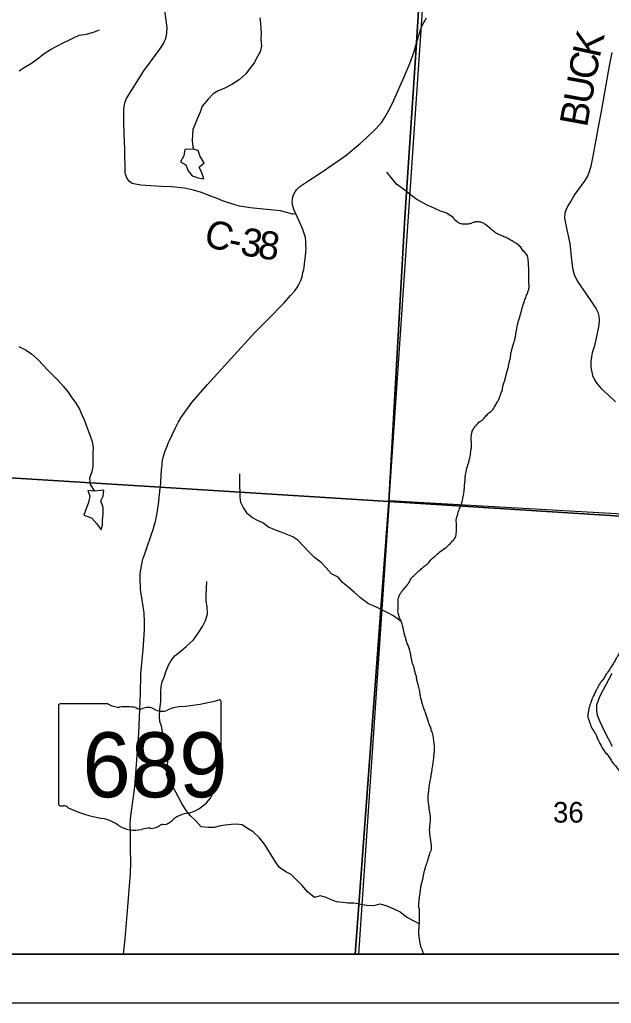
# Model space of a CAD drawing. Extents: x -13.7 to 34, y 0 to 32.3.
# Drawn here: x 24.869 to 26.069, y 14 to 15.995 of the extents above; entities that cross this region are included whole.
import ezdxf

# ---------------------------------------------------------------- set-up
doc = ezdxf.new("R2010")
doc.units = 0
for name, color, linetype in [('GM_X_Corporation', 7, 'Continuous'), ('GM_X_County_Road', 7, 'Continuous'), ('GM_X_County_Road_Text', 7, 'Continuous'), ('GM_X_Minor_Lake', 7, 'Continuous'), ('GM_X_Minor_River', 7, 'Continuous'), ('GM_X_Section_Text', 7, 'Continuous'), ('GM_X_State_Location', 7, 'Continuous'), ('GM_X_State_Route', 7, 'Continuous'), ('GM_X_State_Shield', 7, 'Continuous'), ('GM_X_Township_Road', 7, 'Continuous'), ('GM_X_Township_Road_Text', 7, 'Continuous'), ('SH_Data', 7, 'Continuous')]:
    doc.layers.add(name, color=color, linetype=linetype)

msp = doc.modelspace()

# ---------------------------------------------------------------- linework, layer by layer
at = {"layer": 'GM_X_Corporation'}
for points in [[(23.5167, 20.9), (23.5167, 14.1), (25.5491, 14.1), (25.6174, 15.0182), (25.6502, 15.5943), (25.6733, 15.948), (25.6857, 16.1459)], [(23.5167, 20.9), (23.5167, 15.1495), (24.0951, 15.113), (24.5995, 15.0813), (25.154, 15.0469), (25.6174, 15.0182), (25.6502, 15.5943), (25.6733, 15.948), (25.6857, 16.1459)], [(25.6857, 16.1459), (25.6733, 15.948), (25.6502, 15.5943), (25.6174, 15.0182), (25.5491, 14.1), (30.3167, 14.1)], [(25.6857, 16.1459), (25.6733, 15.948), (25.6502, 15.5943), (25.6174, 15.0182), (26.2581, 14.9774), (26.847, 14.9399), (27.6886, 14.8962), (28.6553, 14.8354)]]:
    msp.add_lwpolyline(points, dxfattribs=at)
for points in [[(25.6876, 16.0444), (26.7165, 15.9781), (26.6464, 14.9606), (25.6185, 15.0191)], [(23.5167, 15.1495), (23.5167, 14.1), (25.5491, 14.1), (25.6174, 15.0182), (25.154, 15.0469), (24.5995, 15.0813), (24.0951, 15.113)], [(25.5491, 14.1), (30.3167, 14.1), (30.3167, 14.7354), (29.7019, 14.7755), (28.6553, 14.8354), (27.6886, 14.8962), (26.847, 14.9399), (26.2581, 14.9774), (25.6174, 15.0182)], [(25.5561, 14.1), (26.5888, 14.1), (26.6464, 14.9606), (25.6185, 15.0191)]]:
    msp.add_lwpolyline(points, close=True, dxfattribs=at)
at = {"layer": 'GM_X_County_Road'}
msp.add_lwpolyline([(25.4287, 15.6011), (25.4223, 15.601), (25.4104, 15.6044), (25.398, 15.6076), (25.3837, 15.6091), (25.3633, 15.6112), (25.3366, 15.6138), (25.315, 15.6171), (25.3053, 15.6197), (25.2824, 15.6271), (25.2657, 15.6338), (25.2523, 15.6384), (25.2374, 15.6444), (25.2212, 15.6497), (25.2029, 15.6538), (25.1769, 15.6559), (25.1559, 15.6567), (25.1237, 15.6588), (25.1149, 15.6597), (25.1036, 15.6613), (25.097, 15.6628), (25.0918, 15.6672), (25.0875, 15.6716), (25.0853, 15.6762), (25.083, 15.6837), (25.082, 15.733), (25.081, 15.7619), (25.0799, 15.7886), (25.0799, 15.8015), (25.0802, 15.814), (25.0823, 15.8267), (25.0853, 15.8354), (25.1208, 15.8912), (25.1435, 15.9225), (25.153, 15.9351), (25.1597, 15.9454), (25.1618, 15.9501), (25.1643, 15.956), (25.1664, 15.9629), (25.1676, 15.9689), (25.1679, 15.9781), (25.1672, 15.9843), (25.1584, 16.0491)], dxfattribs=at)
at = {"layer": 'GM_X_Minor_Lake'}
for points in [[(25.2037, 15.7316), (25.2018, 15.7191), (25.195, 15.7069), (25.2056, 15.7005), (25.2106, 15.6884), (25.2186, 15.6785), (25.2265, 15.676)], [(25.2265, 15.676), (25.2303, 15.6747), (25.242, 15.6725), (25.2382, 15.6846), (25.2329, 15.696), (25.2428, 15.7051), (25.2348, 15.7176), (25.231, 15.7297), (25.2208, 15.7328), (25.2037, 15.7316)], [(25.0393, 15.0406), (25.0208, 15.0388), (25.0068, 15.0399), (25.0109, 15.0285), (25.0082, 15.0156), (25.0037, 15.0028), (24.9987, 14.9902), (25.0142, 14.9849), (25.02, 14.9787)], [(25.02, 14.9787), (25.0256, 14.9728), (25.0339, 14.9602), (25.0369, 14.9697), (25.037, 14.9803), (25.0381, 14.9925), (25.0381, 15.0057), (25.0336, 15.019), (25.0382, 15.0285), (25.0393, 15.0406)]]:
    msp.add_lwpolyline(points, dxfattribs=at)
at = {"layer": 'GM_X_Minor_River'}
for points in [[(25.3557, 15.9992), (25.3572, 15.9874), (25.358, 15.9779), (25.3583, 15.9681), (25.358, 15.9548), (25.3591, 15.9419), (25.3565, 15.9302), (25.3512, 15.9207), (25.3444, 15.9078), (25.335, 15.8952), (25.3274, 15.8857), (25.3138, 15.8732), (25.2994, 15.8637), (25.2839, 15.8557), (25.2714, 15.8508), (25.2615, 15.8447), (25.2513, 15.8337), (25.2392, 15.8196), (25.2347, 15.8079), (25.2294, 15.7953), (25.2241, 15.7821)], [(24.8679, 15.8912), (24.8781, 15.898), (24.8929, 15.9068), (24.905, 15.9159), (24.9186, 15.9269), (24.9311, 15.9349), (24.9444, 15.9413), (24.9569, 15.9482), (24.9675, 15.9527), (24.9781, 15.9584), (24.9894, 15.9638), (25.0042, 15.9661), (25.0208, 15.9703), (25.0307, 15.9744)], [(25.2241, 15.7821), (25.2203, 15.7722), (25.2196, 15.7623), (25.2188, 15.7498), (25.2208, 15.7328)], [(25.6545, 15.6463), (25.6455, 15.653), (25.633, 15.6617), (25.622, 15.6749), (25.6132, 15.6859)], [(25.6545, 15.6463), (25.6753, 15.6302), (25.6949, 15.6199), (25.7077, 15.6142), (25.7214, 15.6074), (25.7347, 15.6033), (25.7472, 15.5953)], [(24.8672, 15.3326), (24.8823, 15.3246), (24.8926, 15.3174), (24.9054, 15.306), (24.9168, 15.2946), (24.9251, 15.2847), (24.9349, 15.2756), (24.947, 15.2631), (24.9576, 15.2513), (24.9674, 15.2399), (24.9753, 15.2274), (24.9825, 15.2175), (24.9901, 15.2053), (24.9957, 15.1924), (25.0002, 15.1822), (25.0036, 15.1727), (25.0078, 15.1621), (25.0127, 15.1491), (25.0157, 15.1393), (25.0179, 15.1268), (25.0171, 15.115), (25.0175, 15.1025), (25.0171, 15.0896), (25.0152, 15.0778), (25.0106, 15.0649), (25.0117, 15.0524)], [(25.5964, 14.8013), (25.5866, 14.806), (25.5764, 14.8106), (25.5601, 14.8227), (25.5472, 14.8337), (25.534, 14.8455), (25.5238, 14.8539), (25.5147, 14.8641), (25.5011, 14.871), (25.4905, 14.8832), (25.4803, 14.8942), (25.4671, 14.9041), (25.4561, 14.9151), (25.444, 14.928), (25.4331, 14.9398), (25.4229, 14.9459), (25.413, 14.9504), (25.399, 14.9558), (25.3861, 14.9603), (25.3733, 14.9661), (25.3623, 14.9744), (25.3513, 14.9797), (25.3407, 14.9851), (25.3309, 14.9927), (25.3222, 15.0064), (25.3177, 15.0158), (25.3162, 15.0268), (25.3162, 15.0371), (25.3155, 15.0496), (25.3151, 15.0625), (25.3152, 15.0743)], [(25.0117, 15.0524), (25.0208, 15.0388)], [(25.5562, 14.2021), (25.5464, 14.203), (25.5342, 14.203), (25.5244, 14.2045), (25.5115, 14.2061), (25.5013, 14.2099), (25.4881, 14.2156), (25.4782, 14.2183), (25.4665, 14.2149), (25.4525, 14.2263), (25.4419, 14.2388), (25.4302, 14.2502), (25.4196, 14.2612), (25.4086, 14.2666), (25.3958, 14.2757), (25.3893, 14.2852), (25.3806, 14.2981), (25.3735, 14.3099), (25.3652, 14.3228), (25.3553, 14.3357), (25.3425, 14.3479), (25.3311, 14.3547), (25.3198, 14.3623), (25.3088, 14.3635), (25.2978, 14.3627), (25.2853, 14.3612), (25.2758, 14.3601), (25.2633, 14.3567), (25.2508, 14.3564), (25.2372, 14.3579), (25.2259, 14.3701), (25.2149, 14.3807), (25.2074, 14.3906), (25.1987, 14.4039), (25.1923, 14.4153), (25.1855, 14.4286), (25.1802, 14.438), (25.1711, 14.451), (25.1666, 14.4639), (25.1681, 14.4783), (25.1693, 14.4889), (25.1705, 14.5033), (25.169, 14.517), (25.1667, 14.5299), (25.1633, 14.5393), (25.1588, 14.5507), (25.1562, 14.5621), (25.1528, 14.5716), (25.1521, 14.5815), (25.1532, 14.597), (25.1548, 14.6118), (25.1548, 14.6323), (25.1556, 14.6425), (25.1575, 14.652), (25.1621, 14.6619), (25.1659, 14.6744), (25.1704, 14.6857), (25.1761, 14.6952), (25.1845, 14.7054), (25.197, 14.716), (25.2065, 14.7236), (25.2213, 14.7376), (25.2308, 14.7509), (25.2399, 14.7641), (25.246, 14.7766), (25.2498, 14.7903), (25.2491, 14.8039), (25.2472, 14.8168), (25.2469, 14.8282), (25.248, 14.8419), (25.2484, 14.8555)], [(25.5964, 14.8013), (25.6146, 14.793), (25.6275, 14.7858), (25.6424, 14.7753)], [(25.5562, 14.2021), (25.5732, 14.1991), (25.5861, 14.1987), (25.6001, 14.2017), (25.6134, 14.1976), (25.6278, 14.1915), (25.6403, 14.1857), (25.6543, 14.1747), (25.6794, 14.1612)]]:
    msp.add_lwpolyline(points, dxfattribs=at)
for points in [[(25.7851, 15.126), (25.7851, 15.1325), (25.7848, 15.1405), (25.7848, 15.1485), (25.7853, 15.1545), (25.7868, 15.1606), (25.7907, 15.1674), (25.7956, 15.1739), (25.8021, 15.1799), (25.809, 15.1852), (25.8151, 15.1924), (25.8216, 15.1984), (25.8288, 15.2052), (25.8342, 15.2143), (25.8388, 15.2219), (25.8419, 15.2287), (25.8446, 15.2363), (25.8477, 15.2443), (25.8485, 15.2503), (25.8504, 15.2568), (25.8527, 15.2636), (25.8547, 15.2712), (25.8563, 15.278), (25.8586, 15.286), (25.8605, 15.2928), (25.8617, 15.2989), (25.8633, 15.3069), (25.8645, 15.313), (25.8656, 15.3205), (25.8672, 15.3266), (25.8688, 15.3335), (25.8715, 15.3422), (25.8738, 15.3498), (25.8754, 15.3581), (25.8762, 15.3646), (25.8777, 15.3718), (25.8793, 15.3801), (25.8809, 15.3862), (25.8836, 15.3946), (25.8855, 15.4006), (25.8871, 15.4075), (25.8913, 15.4207), (25.8944, 15.4298), (25.8979, 15.4386), (25.9002, 15.445), (25.9018, 15.4518), (25.9018, 15.4583), (25.9015, 15.4667), (25.9012, 15.4735), (25.9013, 15.4895), (25.9009, 15.4956), (25.9006, 15.5032), (25.8999, 15.51), (25.8984, 15.5165), (25.8935, 15.523), (25.8871, 15.5302), (25.8811, 15.5379), (25.8732, 15.5432), (25.8656, 15.5475), (25.8573, 15.5521), (25.8486, 15.5559), (25.8422, 15.5586), (25.8361, 15.5617), (25.8278, 15.5678), (25.8142, 15.5793), (25.8074, 15.5832), (25.8002, 15.5851), (25.7942, 15.5851), (25.7866, 15.5829), (25.7805, 15.581), (25.7733, 15.5803), (25.7649, 15.5808), (25.7589, 15.5831), (25.7521, 15.5888), (25.7472, 15.5953)], [(25.7012, 14.3637), (25.702, 14.3709), (25.7013, 14.3838), (25.6995, 14.3934), (25.6988, 14.4013), (25.6977, 14.4082), (25.6973, 14.4147), (25.6982, 14.4283), (25.699, 14.4356), (25.7014, 14.4507), (25.7025, 14.4568), (25.7037, 14.464), (25.7049, 14.4705), (25.7065, 14.4815), (25.7081, 14.4917), (25.7089, 14.5016), (25.7101, 14.5138), (25.7102, 14.5202), (25.7091, 14.5309), (25.7073, 14.5427), (25.7043, 14.553), (25.7017, 14.5606), (25.6987, 14.5686), (25.6961, 14.577), (25.6931, 14.585), (25.6902, 14.5937), (25.6868, 14.6032), (25.6846, 14.6109), (25.6827, 14.6181), (25.6809, 14.6276), (25.6798, 14.6352), (25.6769, 14.6466), (25.6746, 14.6558), (25.6728, 14.6649), (25.6706, 14.6718), (25.6691, 14.6801), (25.6665, 14.6874), (25.6639, 14.6969), (25.6624, 14.7045), (25.6613, 14.711), (25.6591, 14.7197), (25.6558, 14.7281), (25.6528, 14.7365), (25.6509, 14.7441), (25.6483, 14.7521), (25.6472, 14.7586), (25.645, 14.7666), (25.6424, 14.7753), (25.6391, 14.7822), (25.6372, 14.7894), (25.6361, 14.7955), (25.6365, 14.8027), (25.6362, 14.8103), (25.6362, 14.8164), (25.637, 14.8225), (25.6401, 14.8297), (25.644, 14.8357), (25.6493, 14.8418), (25.6562, 14.8501), (25.66, 14.8565), (25.6635, 14.863), (25.6704, 14.8694), (25.6765, 14.8754), (25.6841, 14.8819), (25.6902, 14.8872), (25.6967, 14.8924), (25.7039, 14.9011), (25.712, 14.9079), (25.7211, 14.9159), (25.7303, 14.9223), (25.7367, 14.9275), (25.7432, 14.934), (25.749, 14.9404), (25.7532, 14.9476), (25.7544, 14.9537), (25.7548, 14.9597), (25.7545, 14.9673), (25.7545, 14.9746), (25.7542, 14.9807), (25.7557, 14.9867), (25.7577, 14.9936), (25.7608, 15.0034), (25.765, 15.0137), (25.7669, 15.0209), (25.7689, 15.0307), (25.7705, 15.0406), (25.7709, 15.049), (25.7717, 15.0558), (25.7722, 15.0638), (25.773, 15.0721), (25.7741, 15.0782), (25.778, 15.0926), (25.78, 15.0987), (25.7815, 15.1055), (25.7831, 15.112), (25.7835, 15.1188), (25.7851, 15.126)], [(26.1283, 14.8845), (26.1244, 14.8735), (26.1202, 14.864), (26.1194, 14.8561), (26.119, 14.8496), (26.1178, 14.8424), (26.117, 14.8321), (26.1169, 14.8234), (26.115, 14.8158), (26.1142, 14.8086), (26.1126, 14.7999), (26.1114, 14.7915), (26.1106, 14.785), (26.109, 14.7782), (26.1078, 14.7706), (26.1059, 14.7634), (26.1039, 14.7562), (26.1005, 14.7498), (26.0982, 14.7422), (26.0955, 14.7342), (26.0924, 14.7262), (26.0866, 14.7149), (26.082, 14.7054), (26.0785, 14.6993), (26.0739, 14.691), (26.0686, 14.6827), (26.0632, 14.6736), (26.0582, 14.6675), (26.054, 14.66), (26.0483, 14.6524), (26.0437, 14.6459), (26.0406, 14.6395), (26.0371, 14.6334), (26.0337, 14.6255), (26.0302, 14.6187), (26.0271, 14.6099), (26.0248, 14.6035), (26.0229, 14.5963), (26.0217, 14.5887), (26.0212, 14.5799), (26.0235, 14.5731), (26.0272, 14.5628), (26.0317, 14.554), (26.0366, 14.5472), (26.0392, 14.5407), (26.0429, 14.5327), (26.0467, 14.5251), (26.0515, 14.5163), (26.0572, 14.5083), (26.0628, 14.5014), (26.0681, 14.493), (26.0733, 14.4861), (26.0805, 14.4773), (26.0865, 14.4705), (26.0925, 14.464), (26.1005, 14.4563), (26.1076, 14.4487), (26.1121, 14.4426), (26.1204, 14.4349), (26.1272, 14.4296), (26.1336, 14.4242), (26.1385, 14.4177), (26.1449, 14.4093), (26.1509, 14.4024), (26.1562, 14.3944), (26.1615, 14.3875), (26.1663, 14.3784), (26.1701, 14.3704), (26.1738, 14.3628), (26.1764, 14.3563), (26.1786, 14.3464), (26.1801, 14.3399), (26.182, 14.3308), (26.1834, 14.3236), (26.1845, 14.3175), (26.1856, 14.3114), (26.1856, 14.3023), (26.1863, 14.2931), (26.1877, 14.2848), (26.1888, 14.2775), (26.1891, 14.2688), (26.1898, 14.2593), (26.1902, 14.2532), (26.1909, 14.2444), (26.1916, 14.2384), (26.1946, 14.2285), (26.1976, 14.2224), (26.2024, 14.2117), (26.2058, 14.2052), (26.2099, 14.1983), (26.2133, 14.1922), (26.2189, 14.1846), (26.2227, 14.1777), (26.2272, 14.1716), (26.2305, 14.1613), (26.2328, 14.1534), (26.2339, 14.1469)]]:
    msp.add_spline(points, degree=3, dxfattribs=at)
msp.add_open_spline([(25.6884, 14.1), (25.6878, 14.1017), (25.6872, 14.1033), (25.6866, 14.1049), (25.6855, 14.1078), (25.6842, 14.1105), (25.6832, 14.1133), (25.6822, 14.1163), (25.6816, 14.1194), (25.681, 14.1225), (25.6806, 14.1245), (25.6802, 14.1265), (25.6799, 14.1285), (25.6795, 14.1313), (25.6791, 14.1341), (25.6788, 14.1369), (25.6785, 14.1403), (25.6784, 14.1438), (25.6785, 14.1472), (25.6787, 14.1519), (25.6792, 14.1565), (25.6794, 14.1612), (25.6795, 14.1658), (25.6797, 14.1704), (25.6798, 14.1749), (25.6799, 14.179), (25.6799, 14.183), (25.6799, 14.1871), (25.6799, 14.1911), (25.6777, 14.1949), (25.6781, 14.1989), (25.6783, 14.2017), (25.6786, 14.2044), (25.6789, 14.2072), (25.6792, 14.2101), (25.6794, 14.2131), (25.6797, 14.216), (25.68, 14.2185), (25.6806, 14.221), (25.6809, 14.2236), (25.6812, 14.2256), (25.6814, 14.2276), (25.6817, 14.2296), (25.6823, 14.2337), (25.6829, 14.2378), (25.6837, 14.2418), (25.6841, 14.2439), (25.6852, 14.2458), (25.6856, 14.2479), (25.6864, 14.2515), (25.6868, 14.2552), (25.6876, 14.2589), (25.6883, 14.2622), (25.6891, 14.2655), (25.6899, 14.2687), (25.6908, 14.2721), (25.6916, 14.2753), (25.6926, 14.2786), (25.6935, 14.2814), (25.6949, 14.2841), (25.6957, 14.287), (25.6967, 14.2901), (25.6975, 14.2933), (25.6985, 14.2964), (25.6993, 14.2995), (25.7003, 14.3025), (25.7012, 14.3055), (25.7018, 14.3078), (25.7033, 14.3097), (25.7039, 14.312), (25.7045, 14.3149), (25.7043, 14.3178), (25.7039, 14.3207), (25.7036, 14.3233), (25.7032, 14.3258), (25.7028, 14.3283), (25.7024, 14.3315), (25.7018, 14.3347), (25.7014, 14.3379), (25.701, 14.3405), (25.7009, 14.3432), (25.7007, 14.3458), (25.7005, 14.3485), (25.7001, 14.3512), (25.7003, 14.3538), (25.7006, 14.3571), (25.7009, 14.3604), (25.7012, 14.3637)], degree=3, dxfattribs=at)
at = {"layer": 'GM_X_State_Route'}
for points in [[(25.6735, 15.9475), (25.6819, 15.9745), (25.6859, 15.9845), (25.6942, 15.9987)], [(25.4287, 15.6011), (25.4246, 15.61), (25.422, 15.6197), (25.4217, 15.626), (25.4219, 15.6309), (25.4228, 15.6361), (25.4243, 15.6401), (25.4276, 15.6463), (25.4306, 15.6504), (25.437, 15.6568), (25.4532, 15.6677), (25.4725, 15.6799), (25.4932, 15.6941), (25.5303, 15.7197), (25.5596, 15.7442), (25.5709, 15.7542), (25.5911, 15.7737), (25.5973, 15.7808), (25.6032, 15.7873), (25.6104, 15.798), (25.616, 15.8087), (25.6249, 15.8257), (25.6484, 15.8791), (25.6599, 15.9064), (25.6686, 15.9307), (25.6735, 15.9475)], [(25.0793, 14.1), (25.0825, 14.131), (25.0884, 14.1958), (25.0915, 14.238), (25.0934, 14.2634), (25.0941, 14.2853), (25.0934, 14.3144), (25.0933, 14.3475), (25.0929, 14.3625), (25.0939, 14.3735), (25.0951, 14.385), (25.0982, 14.4095), (25.1008, 14.4288), (25.1026, 14.4394), (25.1105, 14.5478), (25.1126, 14.5957), (25.1137, 14.6283), (25.1145, 14.6679), (25.1159, 14.6833), (25.1195, 14.717), (25.1209, 14.7373), (25.1219, 14.7574), (25.1219, 14.771), (25.1219, 14.7795), (25.1216, 14.7863), (25.1211, 14.7914), (25.1206, 14.7965), (25.1191, 14.805), (25.1162, 14.8266), (25.1147, 14.8335), (25.1141, 14.8412), (25.1136, 14.8477), (25.1129, 14.8574), (25.1129, 14.8641), (25.1132, 14.87), (25.1136, 14.8763), (25.115, 14.8824), (25.116, 14.8876), (25.1177, 14.8975), (25.1193, 14.9033), (25.1217, 14.9094), (25.1293, 14.9321), (25.1327, 14.9418), (25.136, 14.9518), (25.1396, 14.9611), (25.1425, 14.9713), (25.1443, 14.9775), (25.1456, 14.9843), (25.1479, 14.995), (25.1504, 15.0128), (25.1541, 15.0452), (25.1542, 15.0464), (25.1558, 15.0703), (25.1564, 15.0829), (25.1576, 15.0909), (25.1581, 15.0971), (25.1594, 15.1053), (25.161, 15.1121), (25.1631, 15.1189), (25.1677, 15.1303), (25.1703, 15.1362), (25.1728, 15.1418), (25.1846, 15.1671), (25.191, 15.1796), (25.1955, 15.1874), (25.2183, 15.219), (25.2497, 15.255), (25.3459, 15.3605), (25.3705, 15.3858), (25.4053, 15.4208), (25.4183, 15.436), (25.4269, 15.4453), (25.4313, 15.4522), (25.4351, 15.4584), (25.4385, 15.4648), (25.4415, 15.4739), (25.4433, 15.4823), (25.4451, 15.4885), (25.4467, 15.4983), (25.4475, 15.5062), (25.4484, 15.515), (25.4492, 15.5238), (25.4497, 15.5315), (25.4495, 15.5381), (25.4492, 15.5456), (25.4482, 15.5531), (25.4464, 15.5592), (25.4443, 15.5656), (25.4423, 15.5718), (25.4287, 15.6011)]]:
    msp.add_lwpolyline(points, dxfattribs=at)
at = {"layer": 'GM_X_State_Shield'}
for p, q in [((25.0474, 14.6074), (24.9509, 14.6074)), ((25.2773, 14.5077), (25.2773, 14.6123)), ((24.9477, 14.6039), (24.9477, 14.4038)), ((25.2772, 14.5077), (25.2773, 14.5077))]:
    msp.add_line(p, q, dxfattribs=at)
for centre, major_axis, start_param, end_param in [((24.9515, 14.6044), (0.00382, 0), 1.712693, 3.28349), ((25.0704, 14.6306), (0.037, 0), 4.042523, 4.731795), ((25.1599, 14.8802), (0.3495, 0), 4.814394, 5.042369), ((25.2736, 14.6128), (0.00367, 0), 6.141152, 7.989035), ((25.0827, 14.495), (0.133, 0), 1.404758, 1.657858), ((25.1129, 14.6054), (0.0107, 0), 3.836095, 5.185415), ((25.1286, 14.5823), (0.0222, 0), 0.950623, 2.079405), ((25.1572, 14.614), (0.0267, 0), 4.081561, 5.145723), ((25.2044, 14.5463), (0.0703, 0), 1.699011, 2.107814), ((25.2733, 14.5072), (0.00393, 0), 5.05454, 6.418171), ((25.2764, 14.5), (0.00568, 0), 1.883978, 3.671073), ((25.2403, 14.4867), (0.0341, 0), 5.934695, 6.695948), ((25.2904, 14.4638), (0.0248, 0), 2.387724, 3.262537), ((25.1794, 14.4505), (0.0874, 0), 5.101752, 6.440018), ((24.9515, 14.4034), (0.00385, 0), 3.00124, 4.508301), ((24.9521, 14.4239), (0.0294, 0), 4.665946, 4.897461), ((24.9581, 14.3923), (0.0106, 0), 0.519207, 1.627899), ((25.0919, 14.5721), (0.2524, 0), 4.195997, 4.488961), ((25.2163, 14.3476), (0.0479, 0), 1.647645, 2.488434), ((25.0167, 14.3139), (0.079, 0), 0.823519, 1.323587), ((25.1556, 14.3844), (0.0282, 0), 4.937069, 5.64225), ((25.1021, 14.3913), (0.0501, 0), 4.026481, 4.996735), ((25.131, 14.3221), (0.0412, 0), 1.495662, 1.94098), ((25.1347, 14.3763), (0.0267, 0), 4.691044, 5.507374), ((25.1588, 14.3569), (0.00752, 0), 1.147584, 2.315152)]:
    msp.add_ellipse(centre, major_axis=major_axis, ratio=0.8, start_param=start_param, end_param=end_param, dxfattribs=at)
at = {"layer": 'GM_X_Township_Road'}
for points in [[(26.0697, 15.9286), (26.0643, 15.9014), (26.0488, 15.8132), (26.0417, 15.7738), (26.031, 15.7184), (26.0269, 15.6983), (26.0235, 15.6867), (26.0202, 15.678), (26.0151, 15.6691), (26.0074, 15.6587), (25.9948, 15.6413), (25.9865, 15.6271), (25.9814, 15.6188), (25.9772, 15.6104), (25.9747, 15.6033), (25.9741, 15.5928), (25.9788, 15.5692), (25.9843, 15.5415), (25.9871, 15.5147), (25.99, 15.4913), (25.9932, 15.4785), (25.9997, 15.4658), (26.006, 15.4556), (26.0157, 15.4418), (26.0301, 15.4209), (26.0379, 15.4089), (26.0411, 15.4018), (26.0433, 15.3935), (26.0439, 15.386), (26.0433, 15.3757), (26.0395, 15.3558), (26.036, 15.3406), (26.0338, 15.3313), (26.0299, 15.3194), (26.0282, 15.3111), (26.0273, 15.3018), (26.0275, 15.2912), (26.0287, 15.2835), (26.0306, 15.2738), (26.0344, 15.2649), (26.0393, 15.2572), (26.0489, 15.2467), (26.0622, 15.2344), (26.077, 15.2204)], [(26.0699, 14.6689), (26.0517, 14.6346), (26.0454, 14.6232), (26.0427, 14.6163), (26.0387, 14.6049), (26.0386, 14.5943), (26.0403, 14.5844), (26.0454, 14.5717), (26.0547, 14.5514), (26.0707, 14.5213)]]:
    msp.add_lwpolyline(points, dxfattribs=at)
at = {"layer": 'SH_Data'}
for points in [[(23.4167, 21), (30.4167, 21), (30.4167, 14), (23.4167, 14)], [(23.5167, 20.9), (30.3167, 20.9), (30.3167, 14.1), (23.5167, 14.1)]]:
    msp.add_lwpolyline(points, close=True, dxfattribs=at)

# ---------------------------------------------------------------- texts
at = {"layer": 'GM_X_County_Road_Text'}
for s, rotation, p in [('C', 343.3217, (25.2391, 15.5384)), ('3', 350.4047, (25.3141, 15.5186)), ('8', 351.5623, (25.3498, 15.5125)), ('-', 348.3809, (25.2891, 15.5237))]:
    msp.add_text(s, height=0.0568, rotation=rotation, dxfattribs=at).set_placement(p)
at = {"layer": 'GM_X_Section_Text'}
msp.add_text('36', height=0.04186, rotation=0, dxfattribs=at).set_placement((25.9505, 14.3666))
at = {"layer": 'GM_X_State_Location'}
for s in ['s', 'r']:
    msp.add_text(s, height=0.000189, dxfattribs=at).set_placement((25.1088, 14.4906))
msp.add_text('689', height=0.000189, rotation=0, dxfattribs=at).set_placement((25.0419, 14.4768))
at = {"layer": 'GM_X_State_Shield'}
msp.add_text('689', height=0.13184, dxfattribs=at).set_placement((24.9961, 14.4179))
at = {"layer": 'GM_X_Township_Road_Text'}
for s, rotation, p in [('K', 77.6674, (26.0449, 15.916)), ('C', 79.5347, (26.0365, 15.8706)), ('U', 79.7478, (26.0276, 15.8214)), ('B', 79.7491, (26.0193, 15.7755))]:
    msp.add_text(s, height=0.0568, rotation=rotation, dxfattribs=at).set_placement(p)

doc.saveas('drawing.dxf')
